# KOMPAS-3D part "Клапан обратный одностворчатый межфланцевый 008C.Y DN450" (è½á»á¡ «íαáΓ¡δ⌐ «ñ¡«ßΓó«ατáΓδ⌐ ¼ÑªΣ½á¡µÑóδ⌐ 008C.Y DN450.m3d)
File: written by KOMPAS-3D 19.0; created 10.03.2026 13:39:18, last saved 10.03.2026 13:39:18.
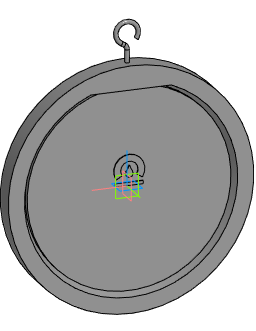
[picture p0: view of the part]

Document properties: Автор: Евгений; Полное имя файла: E:\Dendor\3D для проектировщиков\5.1 Тип 008C. Клапан обратный одностворчатый межфланцевый\stp_Клапан обратный одностворчатый межфланцевый 008C.Y\Клапан обратный одностворчатый межфланцевый 008C.Y DN450.m3d

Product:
- Part/product: Клапан обратный одностворчатый межфланцевый 008C.Y DN450

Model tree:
1. Операция без истории:1  (labels: Клапан обратный одностворчатый межфланцевый 008C.Y DN450)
